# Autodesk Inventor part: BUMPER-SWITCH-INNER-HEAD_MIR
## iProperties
Created: 2007-08
Part Number: BUMPER-SWITCH-INNER-HEAD_MIR
Document SubType Name: Modeling
Density: 1 g/cm^3
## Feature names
1. Derived Body1 [Tagging]
